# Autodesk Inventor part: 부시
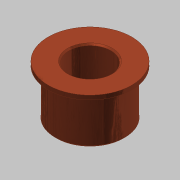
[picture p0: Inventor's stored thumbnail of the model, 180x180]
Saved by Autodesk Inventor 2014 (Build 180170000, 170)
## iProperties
Created: 2015-10
Part Number: 부시
Document SubType Name: Modeling
Designer: mdu
Density: 7.86 g/cm^3
Material: 강철, 연강
Mass: 374.583 g
Surface Area: 131.821 cm^2
Volume: 47.6569 cm^3
Appearance: 구리 - 새틴
Author: mdu
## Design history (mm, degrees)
sketch "스케치1"
  geometry: C1 r 31 at (0, 0) reference; C2 r 25 at (0, 0) reference; C3 r 30 at (0, 0) reference; 1 further point
  node "참조1"
  node "참조2"
  node "참조4"
extrude "돌출1" new body sketch "스케치1" distance "d0" = 3; taper "d1" = 0 deg
extrude "돌출2" join sketch "스케치1" distance "d2" = 36; taper "d3" = 0 deg
chamfer "모따기1" distance "d6" = 1; stored, may be unused: second distance "d7" = 2, angle "d8" = 45 deg
sketch "스케치3"
  geometry: C1 r 15 at (0, 0); 1 further point
  constraints: 1 centre point, 1 coincident
  dimensions: "d13" = 30 diameter of C1
extrude "돌출4" cut sketch "스케치3" stored distance "d14" = 10; taper "d15" = 0 deg
chamfer "모따기3" distance "d16" = 1; stored, may be unused: second distance "d17" = 2, angle "d18" = 45 deg
node "솔리드1"
